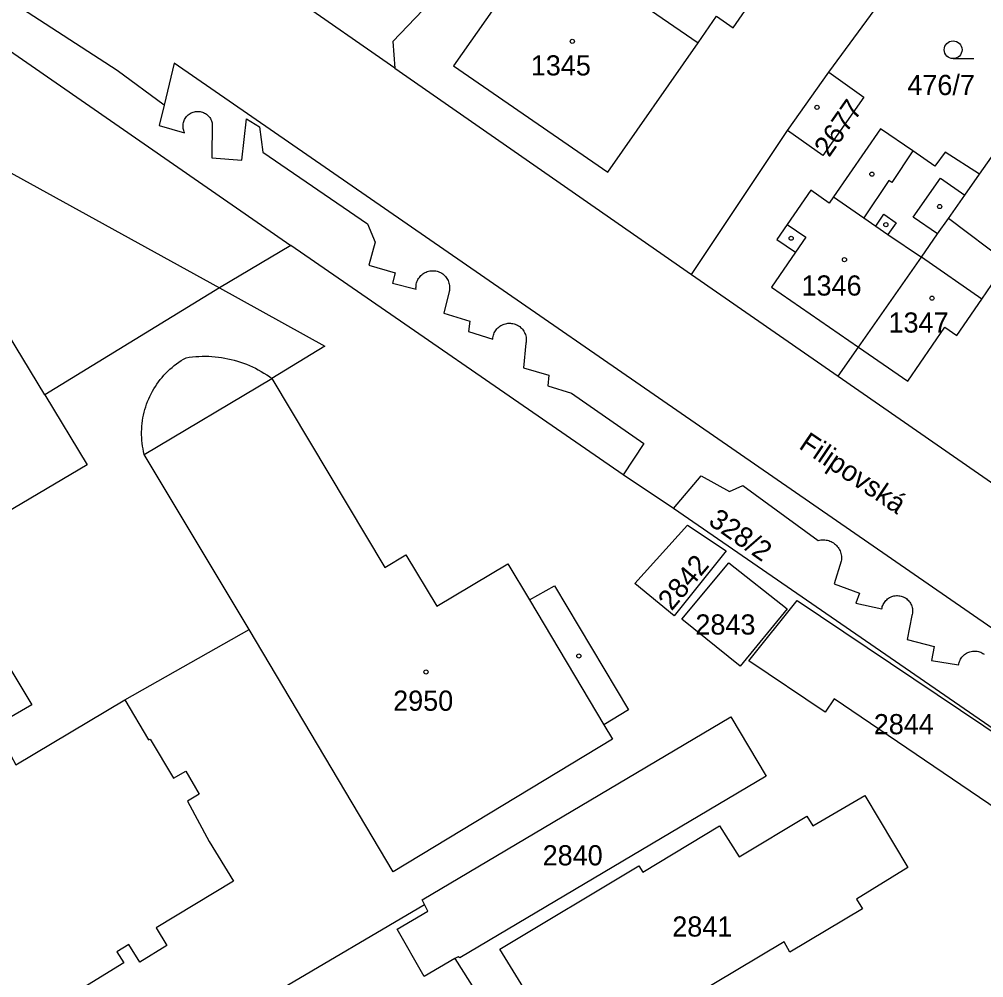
# Model space of a CAD drawing. Extents: x -679220 to -673243, y -1075091 to -1066557.
# Drawn here: x -675822.7 to -675741.4, y -1072325.9 to -1072245.2 of the extents above; entities that cross this region are included whole.
import ezdxf

# ---------------------------------------------------------------- set-up
doc = ezdxf.new("R2010")
doc.units = 0
for name, color, linetype in [('Hranice parcel', 7, 'Continuous'), ('Parcelní čísla', 7, 'Continuous'), ('Pop  PČ popisy', 7, 'Continuous'), ('Vnitřní kresba', 7, 'Continuous'), ('Značky budov', 7, 'Continuous'), ('Značky kultur', 7, 'Continuous')]:
    doc.layers.add(name, color=color, linetype=linetype)

msp = doc.modelspace()

# ---------------------------------------------------------------- linework, layer by layer
at = {"layer": 'Hranice parcel'}
for p, q in [((-675754.47, -1072249.63), (-675745.72, -1072237.63)), ((-675834.37, -1072240.28), (-675799.8, -1072264.22)), ((-675791.03, -1072249.28), (-675801.82, -1072241.76)), ((-675741.76, -1072258.21), (-675734.75, -1072248.23)), ((-675791.03, -1072249.28), (-675766.03, -1072266.66)), ((-675757.95, -1072254.55), (-675754.47, -1072249.63)), ((-675766.03, -1072266.66), (-675757.95, -1072254.55)), ((-675766.03, -1072266.66), (-675753.67, -1072275.25)), ((-675753.67, -1072275.25), (-675751.96, -1072272.79)), ((-675753.67, -1072275.25), (-675740.12, -1072284.65))]:
    msp.add_line(p, q, dxfattribs=at)
for points in [[(-675781.06, -1072236.42), (-675778.46, -1072238.19), (-675786.08, -1072249.09), (-675773.09, -1072258.04), (-675765.47, -1072247.14), (-675763.92, -1072244.91), (-675762.53, -1072245.88), (-675759.11, -1072240.92), (-675763.68, -1072237.74), (-675774.78, -1072229.86)], [(-675781.06, -1072236.42), (-675791.21, -1072247.05), (-675791.03, -1072249.28)], [(-675675.24, -1072344.8), (-675677.06, -1072343.56), (-675675.65, -1072341.45), (-675809.62, -1072248.86), (-675810.47, -1072252.39), (-675814.41, -1072249.48), (-675828.02, -1072240.66), (-675831.19, -1072238.38)], [(-675754.47, -1072249.63), (-675751.51, -1072251.72), (-675754.98, -1072256.65), (-675757.95, -1072254.55)], [(-675741.76, -1072258.21), (-675744.67, -1072256.36), (-675745.53, -1072257.54), (-675747.39, -1072256.26), (-675750.11, -1072254.39), (-675754.07, -1072260.14), (-675754.43, -1072260.66), (-675755.99, -1072259.58), (-675757.98, -1072262.46), (-675758.84, -1072263.72), (-675757.28, -1072264.8), (-675759.3, -1072267.73), (-675751.96, -1072272.79)], [(-675744.38, -1072261.95), (-675743, -1072259.99), (-675741.76, -1072258.21)], [(-675751.96, -1072272.79), (-675746.67, -1072265.22), (-675745.3, -1072263.26), (-675744.38, -1072261.95)], [(-675751.96, -1072272.79), (-675747.81, -1072275.65), (-675744.69, -1072271.12), (-675743.69, -1072271.81), (-675741.58, -1072268.74), (-675739.46, -1072265.66), (-675744.38, -1072261.95)], [(-675799.8, -1072264.22), (-675805.81, -1072267.81), (-675820.53, -1072276.81)], [(-675709.33, -1072326.32), (-675719.29, -1072319.62), (-675722.28, -1072317.61), (-675767.55, -1072286.39), (-675771.79, -1072283.55), (-675799.8, -1072264.22)], [(-675820.53, -1072276.81), (-675827.32, -1072265.63), (-675836.51, -1072271.12), (-675872.16, -1072292.47), (-675867.67, -1072299.93), (-675869.26, -1072300.87), (-675870.69, -1072301.87), (-675866.58, -1072308.98), (-675865.25, -1072311.17), (-675864.04, -1072312.9), (-675838.31, -1072297.5), (-675833.11, -1072306.11)], [(-675781.5, -1072291.05), (-675779.67, -1072294.1), (-675777.58, -1072292.9), (-675771.33, -1072303.35), (-675773.42, -1072304.62), (-675772.69, -1072305.83), (-675791.18, -1072317), (-675803.31, -1072296.58), (-675812.14, -1072281.83), (-675801.38, -1072275.44), (-675791.86, -1072291.37), (-675790.11, -1072290.31), (-675787.48, -1072294.62), (-675781.5, -1072291.05)], [(-675820.53, -1072276.81), (-675816.94, -1072282.72), (-675829.37, -1072290.05), (-675821.61, -1072302.95), (-675824.79, -1072304.77), (-675823.39, -1072307.22)], [(-675766.36, -1072287.81), (-675763.1, -1072289.96), (-675767.49, -1072295.45), (-675770.82, -1072292.72), (-675766.36, -1072287.81)], [(-675761.93, -1072299.67), (-675766.86, -1072295.73), (-675762.9, -1072290.97), (-675757.98, -1072294.84), (-675761.93, -1072299.67)], [(-675754.77, -1072303.57), (-675761.2, -1072299.24), (-675757.12, -1072294.14), (-675733.54, -1072309.98), (-675736.43, -1072314.38), (-675754.01, -1072302.43), (-675754.77, -1072303.57)], [(-675823.39, -1072307.22), (-675822.95, -1072308), (-675813.79, -1072302.53), (-675811.77, -1072305.88), (-675811.63, -1072305.84), (-675809.67, -1072309.11), (-675808.64, -1072308.54), (-675807.51, -1072310.48), (-675808.51, -1072311.06), (-675806.68, -1072314.45), (-675804.62, -1072317.8), (-675811.13, -1072321.73), (-675810.25, -1072323.23), (-675812.52, -1072324.62), (-675813.45, -1072323.13), (-675814.46, -1072323.75), (-675813.87, -1072324.69), (-675818.38, -1072327.47)], [(-675788.52, -1072319.77), (-675788.72, -1072319.37), (-675762.73, -1072303.96), (-675759.75, -1072308.96), (-675785.56, -1072324.26), (-675785.69, -1072324.17), (-675785.98, -1072324.32)], [(-675771.74, -1072332.13), (-675771.88, -1072331.88), (-675775.68, -1072334.13), (-675782.18, -1072323.54), (-675770.47, -1072316.51), (-675770.14, -1072317.05), (-675763.67, -1072313.14), (-675762.01, -1072315.74), (-675756.31, -1072312.33), (-675755.8, -1072313.14), (-675751.43, -1072310.59), (-675747.8, -1072316.66), (-675752.12, -1072319.31), (-675751.64, -1072320.13), (-675757.74, -1072323.78), (-675758.24, -1072322.9), (-675766.17, -1072327.66), (-675765.65, -1072328.52), (-675771.74, -1072332.13)], [(-675779.67, -1072382.96), (-675808.43, -1072331.67), (-675801.04, -1072327.14), (-675788.52, -1072319.77)], [(-675785.98, -1072324.32), (-675788.56, -1072325.83), (-675790.83, -1072321.85), (-675788.24, -1072320.32), (-675788.52, -1072319.77)], [(-675785.98, -1072324.32), (-675779.85, -1072333.99), (-675777.86, -1072332.8), (-675764.69, -1072354.25)]]:
    msp.add_lwpolyline(points, dxfattribs=at)
at = {"layer": 'Vnitřní kresba'}
for p, q in [((-675772.04, -1072242.61), (-675765.47, -1072247.14)), ((-675810.47, -1072252.39), (-675810.89, -1072254.11)), ((-675803.93, -1072257.05), (-675803.52, -1072253.55)), ((-675803.52, -1072253.55), (-675802.43, -1072254.24)), ((-675810.89, -1072254.11), (-675808.74, -1072254.73)), ((-675806.43, -1072253.9), (-675806.46, -1072256.83)), ((-675802.43, -1072254.24), (-675802.14, -1072256.37)), ((-675827.48, -1072255.84), (-675805.81, -1072267.81)), ((-675747.39, -1072256.26), (-675749.16, -1072258.91)), ((-675806.46, -1072256.83), (-675803.93, -1072257.05)), ((-675802.14, -1072256.37), (-675793.34, -1072262.4)), ((-675747.35, -1072261.83), (-675745.05, -1072258.55)), ((-675745.05, -1072258.55), (-675743, -1072259.99)), ((-675749.41, -1072258.74), (-675751.51, -1072261.89)), ((-675749.16, -1072258.91), (-675749.41, -1072258.74)), ((-675754.07, -1072260.14), (-675751.51, -1072261.89)), ((-675751.51, -1072261.89), (-675750.51, -1072262.59)), ((-675750.51, -1072262.59), (-675749.83, -1072261.6)), ((-675749.83, -1072261.6), (-675748.8, -1072262.31)), ((-675745.3, -1072263.26), (-675747.35, -1072261.83)), ((-675793.34, -1072262.4), (-675792.69, -1072263.96)), ((-675757.98, -1072262.46), (-675756.41, -1072263.54)), ((-675750.51, -1072262.59), (-675749.48, -1072263.3)), ((-675748.8, -1072262.31), (-675749.48, -1072263.3)), ((-675756.41, -1072263.54), (-675757.28, -1072264.8)), ((-675749.48, -1072263.3), (-675746.67, -1072265.22)), ((-675792.69, -1072263.96), (-675793.22, -1072265.9)), ((-675793.22, -1072265.9), (-675791, -1072266.54)), ((-675741.58, -1072268.74), (-675746.67, -1072265.22)), ((-675791, -1072266.54), (-675791.22, -1072267.41)), ((-675791.22, -1072267.41), (-675789.24, -1072267.91)), ((-675805.81, -1072267.81), (-675796.93, -1072272.72)), ((-675786.46, -1072268.12), (-675786.9, -1072269.93)), ((-675786.9, -1072269.93), (-675784.71, -1072270.61)), ((-675784.71, -1072270.61), (-675784.81, -1072271.47)), ((-675784.81, -1072271.47), (-675782.78, -1072272.11)), ((-675779.98, -1072272.47), (-675780.2, -1072274.53)), ((-675796.93, -1072272.72), (-675801.38, -1072275.44)), ((-675780.2, -1072274.53), (-675778.05, -1072275.17)), ((-675778.05, -1072275.17), (-675778.14, -1072276.06)), ((-675778.14, -1072276.06), (-675776.14, -1072276.68)), ((-675776.14, -1072276.68), (-675770.04, -1072280.91)), ((-675770.04, -1072280.91), (-675771.79, -1072283.55)), ((-675767.55, -1072286.39), (-675765.22, -1072283.63)), ((-675765.22, -1072283.63), (-675762.82, -1072284.97)), ((-675762.82, -1072284.97), (-675761.7, -1072284.45)), ((-675761.7, -1072284.45), (-675755.35, -1072289.08)), ((-675753.42, -1072290.84), (-675754.02, -1072292.75)), ((-675754.02, -1072292.75), (-675751.89, -1072293.52)), ((-675751.89, -1072293.52), (-675752.2, -1072294.37)), ((-675779.67, -1072294.1), (-675773.42, -1072304.62)), ((-675752.2, -1072294.37), (-675750, -1072294.86)), ((-675747.46, -1072295.42), (-675747.86, -1072297.44)), ((-675813.79, -1072302.53), (-675803.31, -1072296.58)), ((-675747.86, -1072297.44), (-675745.6, -1072298.01)), ((-675745.6, -1072298.01), (-675745.8, -1072299.2)), ((-675745.8, -1072299.2), (-675743.53, -1072299.58))]:
    msp.add_line(p, q, dxfattribs=at)
for points in [[(-675808.74, -1072254.73), (-675808.781, -1072254.641), (-675808.816, -1072254.549), (-675808.842, -1072254.455), (-675808.862, -1072254.359), (-675808.873, -1072254.262), (-675808.877, -1072254.164), (-675808.873, -1072254.066), (-675808.862, -1072253.969), (-675808.843, -1072253.873), (-675808.816, -1072253.779), (-675808.782, -1072253.687), (-675808.741, -1072253.598), (-675808.693, -1072253.513), (-675808.638, -1072253.432), (-675808.577, -1072253.355), (-675808.51, -1072253.284), (-675808.438, -1072253.218), (-675808.361, -1072253.157), (-675808.279, -1072253.104), (-675808.193, -1072253.056), (-675808.104, -1072253.016), (-675808.012, -1072252.983), (-675807.917, -1072252.957), (-675807.821, -1072252.939), (-675807.724, -1072252.929), (-675807.626, -1072252.926), (-675807.528, -1072252.931), (-675807.431, -1072252.943), (-675807.335, -1072252.964), (-675807.241, -1072252.992), (-675807.15, -1072253.027), (-675807.061, -1072253.069), (-675806.977, -1072253.118), (-675806.896, -1072253.174), (-675806.82, -1072253.236), (-675806.749, -1072253.303), (-675806.684, -1072253.376), (-675806.625, -1072253.454), (-675806.572, -1072253.537), (-675806.526, -1072253.623), (-675806.487, -1072253.713), (-675806.455, -1072253.805), (-675806.43, -1072253.9)], [(-675789.24, -1072267.91), (-675789.247, -1072267.805), (-675789.246, -1072267.7), (-675789.237, -1072267.595), (-675789.22, -1072267.491), (-675789.196, -1072267.388), (-675789.164, -1072267.288), (-675789.125, -1072267.19), (-675789.079, -1072267.096), (-675789.025, -1072267.005), (-675788.965, -1072266.918), (-675788.899, -1072266.836), (-675788.827, -1072266.759), (-675788.75, -1072266.688), (-675788.667, -1072266.623), (-675788.58, -1072266.564), (-675788.488, -1072266.512), (-675788.393, -1072266.466), (-675788.295, -1072266.428), (-675788.194, -1072266.397), (-675788.092, -1072266.374), (-675787.987, -1072266.359), (-675787.882, -1072266.351), (-675787.777, -1072266.351), (-675787.672, -1072266.359), (-675787.568, -1072266.375), (-675787.465, -1072266.398), (-675787.365, -1072266.429), (-675787.267, -1072266.467), (-675787.172, -1072266.513), (-675787.08, -1072266.565), (-675786.993, -1072266.624), (-675786.911, -1072266.69), (-675786.833, -1072266.761), (-675786.761, -1072266.838), (-675786.695, -1072266.92), (-675786.636, -1072267.007), (-675786.582, -1072267.098), (-675786.536, -1072267.193), (-675786.497, -1072267.29), (-675786.466, -1072267.391), (-675786.442, -1072267.493), (-675786.425, -1072267.597), (-675786.416, -1072267.702), (-675786.416, -1072267.808), (-675786.423, -1072267.913), (-675786.437, -1072268.017), (-675786.46, -1072268.12)], [(-675782.78, -1072272.11), (-675782.77, -1072272.005), (-675782.752, -1072271.901), (-675782.726, -1072271.799), (-675782.693, -1072271.699), (-675782.653, -1072271.602), (-675782.605, -1072271.508), (-675782.55, -1072271.417), (-675782.489, -1072271.331), (-675782.422, -1072271.25), (-675782.349, -1072271.174), (-675782.27, -1072271.104), (-675782.187, -1072271.04), (-675782.098, -1072270.982), (-675782.006, -1072270.931), (-675781.91, -1072270.887), (-675781.812, -1072270.85), (-675781.71, -1072270.821), (-675781.607, -1072270.799), (-675781.503, -1072270.785), (-675781.398, -1072270.779), (-675781.292, -1072270.781), (-675781.187, -1072270.79), (-675781.083, -1072270.808), (-675780.981, -1072270.833), (-675780.881, -1072270.865), (-675780.783, -1072270.905), (-675780.689, -1072270.952), (-675780.598, -1072271.006), (-675780.512, -1072271.067), (-675780.43, -1072271.134), (-675780.354, -1072271.206), (-675780.283, -1072271.285), (-675780.219, -1072271.368), (-675780.16, -1072271.456), (-675780.109, -1072271.548), (-675780.064, -1072271.643), (-675780.027, -1072271.742), (-675779.997, -1072271.843), (-675779.975, -1072271.946), (-675779.96, -1072272.05), (-675779.953, -1072272.155), (-675779.954, -1072272.261), (-675779.963, -1072272.366), (-675779.98, -1072272.47)], [(-675812.14, -1072281.83), (-675812.195, -1072281.598), (-675812.243, -1072281.364), (-675812.282, -1072281.129), (-675812.314, -1072280.893), (-675812.339, -1072280.655), (-675812.355, -1072280.417), (-675812.363, -1072280.179), (-675812.364, -1072279.94), (-675812.357, -1072279.702), (-675812.342, -1072279.464), (-675812.319, -1072279.226), (-675812.289, -1072278.99), (-675812.25, -1072278.754), (-675812.204, -1072278.52), (-675812.151, -1072278.288), (-675812.089, -1072278.057), (-675812.02, -1072277.829), (-675811.944, -1072277.603), (-675811.86, -1072277.38), (-675811.769, -1072277.159), (-675811.671, -1072276.942), (-675811.565, -1072276.728), (-675811.453, -1072276.518), (-675811.334, -1072276.311), (-675811.208, -1072276.108), (-675811.075, -1072275.91), (-675810.936, -1072275.716), (-675810.791, -1072275.527), (-675810.64, -1072275.343), (-675810.482, -1072275.163), (-675810.319, -1072274.989), (-675810.15, -1072274.821), (-675809.976, -1072274.658), (-675809.797, -1072274.501), (-675809.612, -1072274.35), (-675809.422, -1072274.205), (-675809.228, -1072274.066), (-675809.03, -1072273.934), (-675808.827, -1072273.809), (-675808.62, -1072273.69)], [(-675808.62, -1072273.69), (-675808.35, -1072273.649), (-675808.078, -1072273.616), (-675807.806, -1072273.591), (-675807.534, -1072273.574), (-675807.261, -1072273.564), (-675806.987, -1072273.562), (-675806.714, -1072273.568), (-675806.441, -1072273.582), (-675806.169, -1072273.604), (-675805.897, -1072273.633), (-675805.626, -1072273.671), (-675805.357, -1072273.716), (-675805.089, -1072273.768), (-675804.822, -1072273.829), (-675804.557, -1072273.897), (-675804.295, -1072273.972), (-675804.034, -1072274.055), (-675803.777, -1072274.146), (-675803.521, -1072274.244), (-675803.269, -1072274.349), (-675803.02, -1072274.461), (-675802.774, -1072274.581), (-675802.532, -1072274.707), (-675802.293, -1072274.84), (-675802.059, -1072274.98), (-675801.828, -1072275.127), (-675801.602, -1072275.28), (-675801.38, -1072275.44)], [(-675755.35, -1072289.08), (-675755.242, -1072289.055), (-675755.132, -1072289.039), (-675755.022, -1072289.03), (-675754.911, -1072289.029), (-675754.801, -1072289.036), (-675754.691, -1072289.05), (-675754.583, -1072289.073), (-675754.476, -1072289.103), (-675754.372, -1072289.141), (-675754.271, -1072289.186), (-675754.173, -1072289.238), (-675754.079, -1072289.297), (-675753.99, -1072289.362), (-675753.905, -1072289.434), (-675753.826, -1072289.511), (-675753.753, -1072289.594), (-675753.685, -1072289.682), (-675753.625, -1072289.775), (-675753.57, -1072289.872), (-675753.523, -1072289.972), (-675753.483, -1072290.075), (-675753.451, -1072290.181), (-675753.426, -1072290.289), (-675753.409, -1072290.398), (-675753.4, -1072290.509), (-675753.399, -1072290.62), (-675753.406, -1072290.73), (-675753.42, -1072290.84)], [(-675750, -1072294.86), (-675749.983, -1072294.761), (-675749.958, -1072294.664), (-675749.925, -1072294.57), (-675749.886, -1072294.477), (-675749.839, -1072294.389), (-675749.786, -1072294.304), (-675749.727, -1072294.223), (-675749.661, -1072294.147), (-675749.59, -1072294.077), (-675749.514, -1072294.012), (-675749.433, -1072293.953), (-675749.347, -1072293.901), (-675749.258, -1072293.855), (-675749.166, -1072293.816), (-675749.071, -1072293.785), (-675748.974, -1072293.76), (-675748.875, -1072293.744), (-675748.775, -1072293.735), (-675748.675, -1072293.733), (-675748.575, -1072293.74), (-675748.476, -1072293.754), (-675748.378, -1072293.775), (-675748.282, -1072293.804), (-675748.189, -1072293.841), (-675748.098, -1072293.884), (-675748.012, -1072293.934), (-675747.929, -1072293.991), (-675747.851, -1072294.054), (-675747.778, -1072294.122), (-675747.71, -1072294.196), (-675747.649, -1072294.275), (-675747.593, -1072294.359), (-675747.545, -1072294.446), (-675747.503, -1072294.537), (-675747.468, -1072294.631), (-675747.44, -1072294.727), (-675747.42, -1072294.825), (-675747.408, -1072294.925), (-675747.403, -1072295.025), (-675747.406, -1072295.125), (-675747.416, -1072295.225), (-675747.434, -1072295.323), (-675747.46, -1072295.42)], [(-675743.53, -1072299.58), (-675743.512, -1072299.478), (-675743.486, -1072299.378), (-675743.453, -1072299.28), (-675743.412, -1072299.185), (-675743.364, -1072299.093), (-675743.31, -1072299.005), (-675743.248, -1072298.921), (-675743.181, -1072298.843), (-675743.108, -1072298.77), (-675743.029, -1072298.702), (-675742.946, -1072298.641), (-675742.858, -1072298.586), (-675742.766, -1072298.538), (-675742.671, -1072298.498), (-675742.573, -1072298.464), (-675742.473, -1072298.438), (-675742.371, -1072298.42), (-675742.268, -1072298.41), (-675742.164, -1072298.407), (-675742.061, -1072298.413), (-675741.958, -1072298.426), (-675741.857, -1072298.447), (-675741.758, -1072298.476), (-675741.661, -1072298.512), (-675741.567, -1072298.555), (-675741.476, -1072298.606), (-675741.39, -1072298.663)]]:
    msp.add_lwpolyline(points, dxfattribs=at)
at = {"layer": 'Značky budov'}
for centre in [(-675776.077, -1072247.029), (-675755.457, -1072252.589), (-675750.837, -1072258.219), (-675745.127, -1072260.949), (-675749.657, -1072262.479), (-675757.637, -1072263.619), (-675753.147, -1072265.429), (-675745.767, -1072268.669), (-675775.527, -1072298.819), (-675788.407, -1072300.169)]:
    msp.add_circle(centre, 0.175, dxfattribs=at)
at = {"layer": 'Značky kultur'}
msp.add_line((-675743.993, -1072248.48), (-675742.243, -1072248.48), dxfattribs=at)
msp.add_circle((-675743.993, -1072247.73), 0.75, dxfattribs=at)

# ---------------------------------------------------------------- texts
at = {"layer": 'Parcelní čísla'}
for s, p in [('1345', (-675779.574, -1072249.9)), ('476/7', (-675747.848, -1072251.55)), ('1346', (-675756.764, -1072268.45)), ('1347', (-675749.434, -1072271.57)), ('2843', (-675765.704, -1072297.019)), ('2950', (-675791.17, -1072303.44)), ('2844', (-675750.674, -1072305.42)), ('2840', (-675778.574, -1072316.47)), ('2841', (-675767.654, -1072322.47))]:
    msp.add_text(s, height=1.7, dxfattribs=at).set_placement(p)
for s, rotation, p in [('2677', 55, (-675754.439, -1072256.863)), ('328/2', 325, (-675764.709, -1072287.674)), ('2842', 50, (-675767.71, -1072295.084))]:
    msp.add_text(s, height=1.7, rotation=rotation, dxfattribs=at).set_placement(p)
at = {"layer": 'Pop  PČ popisy'}
msp.add_text('Filipovská', height=1.7, rotation=326, dxfattribs=at).set_placement((-675757.079, -1072281.275))

doc.saveas('drawing.dxf')
